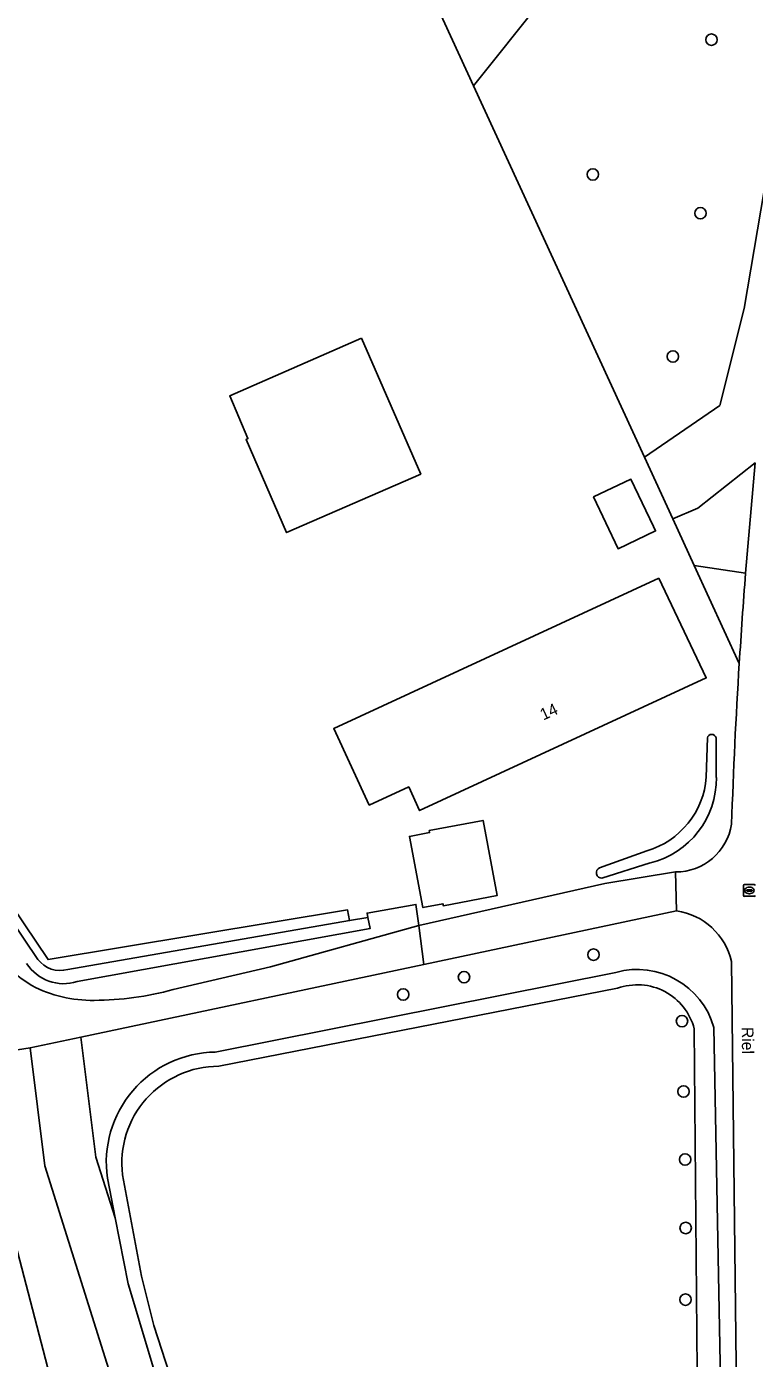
# Model space of a CAD drawing. Extents: x 163859 to 164644, y 379566 to 382155.
# Drawn here: x 164380.2 to 164442.4, y 381567 to 381680.8 of the extents above; entities that cross this region are included whole.
import ezdxf

# ---------------------------------------------------------------- set-up
doc = ezdxf.new("R2010")
doc.units = 0
for name, color, linetype in [('IMGEO_Boom', 7, 'Continuous'), ('IMGEO_Erf', 7, 'Continuous'), ('IMGEO_Grasland_overig', 7, 'Continuous'), ('IMGEO_Greppel_droge_sloot', 7, 'Continuous'), ('IMGEO_Groenvoorziening', 7, 'Continuous'), ('IMGEO_Haag', 7, 'Continuous'), ('IMGEO_Hek', 7, 'Continuous'), ('IMGEO_Loofbos', 7, 'Continuous'), ('IMGEO_Open_loods', 7, 'Continuous'), ('IMGEO_Openbare_ruimte_label', 7, 'Continuous'), ('IMGEO_Pand', 7, 'Continuous'), ('IMGEO_Pand_nummerreeks', 7, 'Continuous'), ('IMGEO_Rijbaan_lokaal_gesloten', 7, 'Continuous'), ('IMGEO_Rijbaan_lokaal_halfverhard', 7, 'Continuous'), ('IMGEO_Rijbaan_lokaal_onverhard', 7, 'Continuous'), ('IMGEO_Rioolput', 7, 'Continuous'), ('IMGEO_Voetpad_open', 7, 'Continuous'), ('IMGEO_Waterloop', 7, 'Continuous')]:
    doc.layers.add(name, color=color, linetype=linetype)

msp = doc.modelspace()

# ---------------------------------------------------------------- linework, layer by layer
at = {"layer": 'IMGEO_Boom'}
for centre in [(164438.71, 381679.7), (164428.58, 381668.19), (164437.77, 381664.87), (164435.42, 381652.63), (164428.64, 381601.52), (164417.58, 381599.6), (164412.38, 381598.12), (164436.2, 381595.85), (164436.33, 381589.83), (164436.46, 381584.02), (164436.51, 381578.17), (164436.5, 381572.05)]:
    msp.add_circle(centre, 0.489, dxfattribs=at)
at = {"layer": 'IMGEO_Erf'}
for points in [[(164441.09, 381626.39), (164437.24, 381634.76), (164435.4, 381638.77), (164432.98, 381644.03), (164418.39, 381675.76), (164404.83, 381705.27)], [(164337.65, 381665.82), (164338.35, 381664.78), (164338.92, 381665.18), (164382.05, 381601.1), (164407.63, 381605.35), (164407.8, 381604.43), (164409.37, 381604.7), (164409.29, 381605.07), (164413.47, 381605.82), (164413.71, 381604.01), (164429.61, 381607.59), (164435.64, 381608.59)], [(164438.27, 381616.7), (164438.38, 381620.04)], [(164439.11, 381620.04), (164439.12, 381616.67)], [(164429.16, 381608.94), (164433.18, 381610.4)], [(164433.49, 381609.38), (164429.36, 381608.07)], [(164380.24, 381495.98), (164399.71, 381501.75), (164399.68, 381501.92), (164397.93, 381501.62), (164394.23, 381519.23), (164377.05, 381585.25)]]:
    msp.add_lwpolyline(points, dxfattribs=at)
for points in [[(164408.82, 381654.19), (164413.88, 381642.59), (164402.42, 381637.59), (164398.96, 381645.55), (164399.12, 381645.62), (164397.56, 381649.26)], [(164431.84, 381642.15), (164433.76, 381638.1), (164433.94, 381637.73), (164430.73, 381636.21), (164428.64, 381640.63)], [(164434.22, 381633.69), (164438.27, 381625.17), (164413.78, 381613.84), (164412.85, 381615.86), (164409.48, 381614.3), (164406.45, 381620.84)], [(164412.91, 381611.62), (164414.64, 381611.95), (164414.61, 381612.12), (164419.21, 381612.99), (164420.42, 381606.58), (164415.82, 381605.7), (164415.78, 381605.88), (164414.06, 381605.55)]]:
    msp.add_lwpolyline(points, close=True, dxfattribs=at)
for centre, radius, start, end in [((164930.76, 381596.32), 490.6, 176.4854, 178.0894), ((164438.74, 381619.97), 0.374, 10.7468, 169.8768), ((164431.19, 381617.21), 7.1, 286.3074, 355.8959), ((164431.74, 381616.55), 7.39, 283.7517, 0.901), ((164435.65, 381613.44), 4.85, 269.9071, 350.8532), ((164429.33, 381608.52), 0.455, 112.0307, 273.6908)]:
    msp.add_arc(centre, radius, start, end, dxfattribs=at)
at = {"layer": 'IMGEO_Grasland_overig'}
msp.add_lwpolyline([(164392.11, 381552.47), (164390.65, 381553.68), (164390.08, 381554.71), (164388.77, 381561.19), (164381.76, 381583.47), (164380.51, 381593.56), (164377.23, 381593.05), (164374.37, 381592.06), (164375.48, 381589.55), (164377.05, 381585.25), (164394.23, 381519.23), (164389.32, 381551.69)], close=True, dxfattribs=at)
at = {"layer": 'IMGEO_Greppel_droge_sloot'}
for points in [[(164438.38, 381620.04), (164438.27, 381616.7)], [(164439.12, 381616.67), (164439.11, 381620.04)], [(164433.18, 381610.4), (164429.16, 381608.94)], [(164429.36, 381608.07), (164433.49, 381609.38)]]:
    msp.add_lwpolyline(points, dxfattribs=at)
for centre, radius, start, end in [((164438.74, 381619.97), 0.374, 10.7468, 169.8768), ((164431.19, 381617.21), 7.1, 286.3074, 355.8959), ((164431.74, 381616.55), 7.39, 283.7517, 0.901), ((164429.33, 381608.52), 0.455, 112.0307, 273.6908)]:
    msp.add_arc(centre, radius, start, end, dxfattribs=at)
at = {"layer": 'IMGEO_Groenvoorziening'}
for points in [[(164413.49, 381705.55), (164411.5, 381706.9), (164410.18, 381704.99), (164411.4, 381704.13), (164412.89, 381702.27), (164413.63, 381703.36), (164430.23, 381692.16), (164429.46, 381691.02), (164430.17, 381690.54), (164431.15, 381689.85), (164431.93, 381691.02), (164445.15, 381682.31), (164445.86, 381681.3), (164445.51, 381680.44), (164441.51, 381656.72), (164439.43, 381648.45), (164432.98, 381644.03), (164435.4, 381638.77), (164437.55, 381639.66), (164442.44, 381643.54)], [(164383.73, 381600.26), (164407.8, 381604.43), (164407.63, 381605.35), (164382.05, 381601.1), (164338.92, 381665.18), (164338.35, 381664.78)], [(164338.35, 381664.78), (164381.18, 381601.12)], [(164441.62, 381634.12), (164437.24, 381634.76), (164441.09, 381626.39)], [(164392.72, 381598.54), (164401.06, 381600.47), (164413.71, 381604.01), (164413.47, 381605.82), (164409.29, 381605.07), (164409.37, 381604.7), (164409.57, 381603.76), (164384.53, 381599.22)], [(164435.74, 381605.27), (164414.14, 381600.68), (164384.86, 381594.48), (164386.14, 381584.23), (164387.77, 381579.05), (164387.11, 381582.42)], [(164437.62, 381342.51), (164440.93, 381376.03), (164442.03, 381410.67), (164442.31, 381432.69), (164442.26, 381444.54), (164442.24, 381448.35), (164442.22, 381457.68), (164442.22, 381458.62), (164442.05, 381465.53), (164441.98, 381468.27), (164441.6, 381500), (164440.42, 381600.95)], [(164396.33, 381593.2), (164430.54, 381600.01)], [(164438.92, 381595.29), (164439.69, 381554.54), (164440.38, 381500), (164440.38, 381499.71), (164438.34, 381499.7), (164438.46, 381494.53)]]:
    msp.add_lwpolyline(points, dxfattribs=at)
for points in [[(164412.89, 381702.27), (164411.4, 381704.13), (164411.01, 381703.55), (164410.64, 381703), (164408.97, 381700.56), (164406.53, 381702.22), (164408.2, 381704.66), (164408.26, 381704.62), (164408.63, 381705.17), (164406.93, 381706.32), (164404.83, 381705.27), (164418.39, 381675.76), (164430.17, 381690.54), (164429.46, 381691.02)], [(164445.51, 381680.44), (164431.15, 381689.85), (164430.17, 381690.54), (164418.39, 381675.76), (164432.98, 381644.03), (164439.43, 381648.45), (164441.51, 381656.72)], [(164395.86, 381553.52), (164391.32, 381565.35), (164388.89, 381573.41), (164387.77, 381579.05), (164386.14, 381584.23), (164384.86, 381594.48), (164380.51, 381593.56), (164381.76, 381583.47), (164388.77, 381561.19), (164390.08, 381554.71), (164390.65, 381553.68), (164392.11, 381552.47)]]:
    msp.add_lwpolyline(points, close=True, dxfattribs=at)
for centre, radius, start, end in [((164923.89, 381596.75), 483.71, 175.569, 176.4873), ((164434.91, 381599.68), 5.65, 12.9621, 81.5794), ((164386.24, 381608.19), 10.85, 208.3188, 239.0619), ((164383.08, 381602.55), 2.38, 216.8405, 285.7795), ((164383.39, 381602.82), 3.78, 212.9561, 287.5967), ((164432.36, 381593.44), 6.82, 15.7877, 105.4552), ((164385.9, 381609.07), 11.46, 242.7973, 270.3915), ((164385.95, 381623.04), 25.42, 270.0677, 285.4619), ((164396.45, 381583.77), 9.43, 90.7194, 188.1954)]:
    msp.add_arc(centre, radius, start, end, dxfattribs=at)
at = {"layer": 'IMGEO_Haag'}
for points in [[(164383.73, 381600.26), (164407.8, 381604.43), (164407.63, 381605.35), (164382.05, 381601.1), (164338.92, 381665.18), (164338.35, 381664.78)], [(164338.35, 381664.78), (164381.18, 381601.12)]]:
    msp.add_lwpolyline(points, dxfattribs=at)
msp.add_arc((164383.08, 381602.55), 2.38, 216.8405, 285.7795, dxfattribs=at)
at = {"layer": 'IMGEO_Hek'}
for points in [[(164430.17, 381690.54), (164418.39, 381675.76)], [(164445.51, 381680.44), (164441.51, 381656.72), (164439.43, 381648.45), (164432.98, 381644.03)]]:
    msp.add_lwpolyline(points, dxfattribs=at)
at = {"layer": 'IMGEO_Loofbos'}
for points in [[(164430.68, 381598.65), (164396.62, 381591.99)], [(164438.46, 381494.53), (164438.34, 381499.7), (164438.34, 381500), (164437.6, 381552.99), (164437.24, 381595.18)], [(164388.41, 381582.72), (164390.02, 381574.06), (164391.09, 381569.85), (164392.41, 381565.7), (164407.87, 381524.82), (164407.05, 381524.34), (164395.86, 381553.52), (164392.11, 381552.47), (164389.32, 381551.69), (164394.23, 381519.23), (164397.93, 381501.62), (164399.68, 381501.92), (164399.71, 381501.75), (164401.6, 381502.3), (164404.9, 381489.96), (164405.2, 381487.7), (164404.81, 381487.67), (164403.46, 381487.71), (164404.03, 381484.15)]]:
    msp.add_lwpolyline(points, dxfattribs=at)
for centre, radius, start, end in [((164432.39, 381593.94), 5.01, 14.3554, 109.9592), ((164396.63, 381583.71), 8.28, 90.0584, 186.8881)]:
    msp.add_arc(centre, radius, start, end, dxfattribs=at)
at = {"layer": 'IMGEO_Open_loods'}
msp.add_lwpolyline([(164408.82, 381654.19), (164397.56, 381649.26), (164399.12, 381645.62), (164398.96, 381645.55), (164402.42, 381637.59), (164413.88, 381642.59)], close=True, dxfattribs=at)
at = {"layer": 'IMGEO_Pand'}
for points in [[(164433.76, 381638.1), (164431.84, 381642.15), (164428.64, 381640.63), (164430.73, 381636.21), (164433.94, 381637.73)], [(164434.22, 381633.69), (164406.45, 381620.84), (164409.48, 381614.3), (164412.85, 381615.86), (164413.78, 381613.84), (164438.27, 381625.17)], [(164414.06, 381605.55), (164415.78, 381605.88), (164415.82, 381605.7), (164420.42, 381606.58), (164419.21, 381612.99), (164414.61, 381612.12), (164414.64, 381611.95), (164412.91, 381611.62)]]:
    msp.add_lwpolyline(points, close=True, dxfattribs=at)
at = {"layer": 'IMGEO_Rijbaan_lokaal_gesloten'}
for points in [[(164442.44, 381643.54), (164441.62, 381634.12)], [(164435.64, 381608.59), (164435.74, 381605.27)], [(164440.42, 381600.95), (164441.6, 381500), (164441.98, 381468.27), (164442.05, 381465.53), (164442.22, 381458.62), (164442.22, 381457.68), (164445.79, 381457.7)]]:
    msp.add_lwpolyline(points, dxfattribs=at)
for centre, radius, start, end in [((164923.89, 381596.75), 483.71, 175.569, 176.4873), ((164930.76, 381596.32), 490.6, 176.4854, 178.0894), ((164435.65, 381613.44), 4.85, 269.9071, 350.8532), ((164434.91, 381599.68), 5.65, 12.9621, 81.5794)]:
    msp.add_arc(centre, radius, start, end, dxfattribs=at)
at = {"layer": 'IMGEO_Rijbaan_lokaal_halfverhard'}
msp.add_lwpolyline([(164413.71, 381604.01), (164414.14, 381600.68), (164435.74, 381605.27), (164435.64, 381608.59), (164429.61, 381607.59)], close=True, dxfattribs=at)
at = {"layer": 'IMGEO_Rijbaan_lokaal_onverhard'}
for points in [[(164414.14, 381600.68), (164413.71, 381604.01), (164401.06, 381600.47), (164392.72, 381598.54)], [(164376.28, 381594.59), (164373.62, 381593.79), (164374.37, 381592.06), (164377.23, 381593.05), (164380.51, 381593.56), (164384.86, 381594.48), (164414.14, 381600.68)]]:
    msp.add_lwpolyline(points, dxfattribs=at)
for centre, radius, start, end in [((164386.24, 381608.19), 10.85, 208.3188, 239.0619), ((164385.9, 381609.07), 11.46, 242.7973, 270.3915), ((164385.95, 381623.04), 25.42, 270.0677, 285.4619)]:
    msp.add_arc(centre, radius, start, end, dxfattribs=at)
at = {"layer": 'IMGEO_Rioolput'}
for p, q in [((164441.45, 381606.58), (164441.45, 381607.43)), ((164441.52, 381607.51), (164442.38, 381607.51)), ((164441.71, 381607), (164441.71, 381607.01)), ((164441.75, 381607.05), (164442.15, 381607.05)), ((164442.15, 381606.96), (164441.75, 381606.96)), ((164441.94, 381607.29), (164441.96, 381607.29)), ((164441.96, 381606.73), (164441.94, 381606.73)), ((164442.19, 381607.01), (164442.19, 381607)), ((164442.38, 381606.51), (164441.52, 381606.51))]:
    msp.add_line(p, q, dxfattribs=at)
for points in [[(164441.45, 381606.58), (164441.45, 381607.43)], [(164441.52, 381607.51), (164442.38, 381607.51)], [(164442.38, 381606.51), (164441.52, 381606.51)]]:
    msp.add_lwpolyline(points, dxfattribs=at)
for centre, radius, start, end in [((164441.53, 381607.43), 0.0765, 91.552, 178.448), ((164441.53, 381607.43), 0.0765, 91.552, 178.448), ((164441.53, 381606.58), 0.0765, 181.552, 268.448), ((164441.53, 381606.58), 0.0765, 181.552, 268.448), ((164441.75, 381607.01), 0.0403, 85.8775, 175.7526), ((164441.75, 381607), 0.0366, 178.938, 274.7102), ((164442.15, 381607.01), 0.0386, 1.7309, 96.639), ((164442.15, 381607.01), 0.043, 264.8664, 352.4533), ((164442.37, 381607.43), 0.0765, 1.552, 88.448), ((164442.37, 381607.43), 0.0765, 1.552, 88.448), ((164442.37, 381606.58), 0.0765, 271.552, 358.448), ((164442.37, 381606.58), 0.0765, 271.552, 358.448)]:
    msp.add_arc(centre, radius, start, end, dxfattribs=at)
for centre, major_axis, ratio, start_param, end_param in [((164441.94, 381607.01), (-0.387, 0.002), 0.722429, 4.712389, 7.853982), ((164441.96, 381607.01), (-0.39, 0.002), 0.717154, 1.570796, 4.712389)]:
    msp.add_ellipse(centre, major_axis=major_axis, ratio=ratio, start_param=start_param, end_param=end_param, dxfattribs=at)
at = {"layer": 'IMGEO_Voetpad_open'}
msp.add_lwpolyline([(164435.4, 381638.77), (164437.24, 381634.76), (164441.62, 381634.12), (164442.44, 381643.54), (164437.55, 381639.66)], close=True, dxfattribs=at)
at = {"layer": 'IMGEO_Waterloop'}
for points in [[(164381.18, 381601.12), (164338.35, 381664.78)], [(164384.53, 381599.22), (164409.57, 381603.76), (164409.37, 381604.7), (164407.8, 381604.43), (164383.73, 381600.26)], [(164430.54, 381600.01), (164396.33, 381593.2)], [(164396.62, 381591.99), (164430.68, 381598.65)], [(164437.24, 381595.18), (164437.6, 381552.99), (164438.34, 381500), (164438.34, 381499.7), (164440.38, 381499.71), (164440.38, 381500), (164439.69, 381554.54)], [(164439.69, 381554.54), (164438.92, 381595.29)], [(164387.11, 381582.42), (164387.77, 381579.05), (164388.89, 381573.41), (164391.32, 381565.35), (164395.86, 381553.52), (164407.05, 381524.34), (164407.87, 381524.82), (164392.41, 381565.7), (164391.09, 381569.85), (164390.02, 381574.06), (164388.41, 381582.72)]]:
    msp.add_lwpolyline(points, dxfattribs=at)
for centre, radius, start, end in [((164383.08, 381602.55), 2.38, 216.8405, 285.7795), ((164383.39, 381602.82), 3.78, 212.9561, 287.5967), ((164432.36, 381593.44), 6.82, 15.7877, 105.4552), ((164432.39, 381593.94), 5.01, 14.3554, 109.9592), ((164396.45, 381583.77), 9.43, 90.7194, 188.1954), ((164396.63, 381583.71), 8.28, 90.0584, 186.8881)]:
    msp.add_arc(centre, radius, start, end, dxfattribs=at)

# ---------------------------------------------------------------- texts
at = {"layer": 'IMGEO_Openbare_ruimte_label'}
msp.add_text('Riel', height=1, rotation=270.5156, dxfattribs=at).set_placement((164441.3, 381595.34))
at = {"layer": 'IMGEO_Pand_nummerreeks'}
msp.add_text('14', height=1, rotation=24.884, dxfattribs=at).set_placement((164424.35, 381621.52))

doc.saveas('drawing.dxf')
